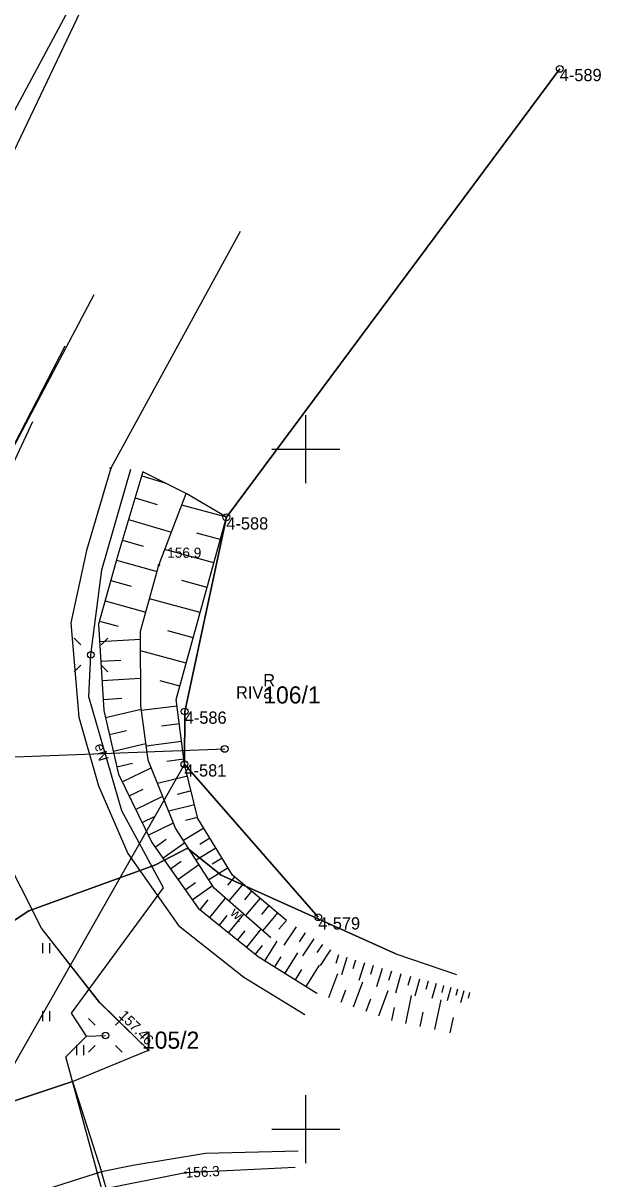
# Model space of a CAD drawing. Extents: x 5598798 to 5599616, y 5661498 to 5662453.
# Drawn here: x 5599229.2 to 5599271.7, y 5662046.3 to 5662131.3 of the extents above; entities that cross this region are included whole.
import ezdxf

# ---------------------------------------------------------------- set-up
doc = ezdxf.new("R2010")
doc.units = 0
for name, color, linetype in [('BUBZ_L_1', 7, 'Continuous'), ('Dzialki', 7, 'Continuous'), ('Kontury', 7, 'Continuous'), ('KTJZ_L_0', 7, 'Continuous'), ('KTKR_L_0', 7, 'Continuous'), ('Numery_dzialek', 7, 'Continuous'), ('Numery_konturow', 7, 'Continuous'), ('Numery_punktow', 7, 'Continuous'), ('Numery_uzytkow', 7, 'Continuous'), ('Podzial_sekcyjny_krzyze', 7, 'Continuous'), ('PTRW_E_T_0', 7, 'Continuous'), ('PTRW_L_1', 7, 'Continuous'), ('PTTU_L_2', 7, 'Continuous'), ('Punkty', 7, 'Continuous'), ('RTPW_T_0', 7, 'Continuous'), ('RTPW_T_1', 7, 'Continuous'), ('SUOE_L_1', 7, 'Continuous'), ('SUOW_L_0', 7, 'Continuous'), ('SUPE_E_T_3', 7, 'Continuous'), ('SUPE_L_3', 7, 'Continuous'), ('SUPT_L_0', 7, 'Continuous'), ('SUPW_L_0', 7, 'Continuous'), ('SUSM_T_0', 7, 'Continuous'), ('SUSM_T_3', 7, 'Continuous'), ('SUTE_T_0', 7, 'Continuous'), ('Uzytki', 7, 'Continuous')]:
    doc.layers.add(name, color=color, linetype=linetype)

# ---------------------------------------------------------------- blocks, each defined once
blk = doc.blocks.new('GRT')
blk.add_circle((0, 0), 0.25)
blk = doc.blocks.new('POINT_DISPLAY')
blk.add_line((0, 0), (0, 0))
blk = doc.blocks.new('2_PTTU04')
for p, q in [((-0.2625, -0.375), (-0.2625, 0.375)), ((0.2625, -0.375), (0.2625, 0.375))]:
    blk.add_line(p, q)
blk = doc.blocks.new('2_RTPW02')
blk.add_circle((0, 0), 0.045)
blk = doc.blocks.new('2_RTPW01')
blk.add_circle((0, 0), 0.045)
blk = doc.blocks.new('4_SUSM04_01')
blk.add_circle((0, 0), 0.25)
blk = doc.blocks.new('4_SUSM01')
for p, q in [((-0.74249, 0.74249), (-1.23746, 1.23746)), ((0.74249, 0.74249), (1.23746, 1.23746)), ((-0.74249, -0.74249), (-1.23746, -1.23746)), ((0.74249, -0.74249), (1.23746, -1.23746))]:
    blk.add_line(p, q)
blk.add_circle((0, 0), 0.245)
blk = doc.blocks.new('4_SUPS01_03')
blk.add_circle((0, 0), 0.0625)

msp = doc.modelspace()

# ---------------------------------------------------------------- linework, layer by layer
at = {"layer": 'BUBZ_L_1'}
for p, q in [((5599238.041933, 5662098.343835), (5599236.200458, 5662092.209108)), ((5599241.209969, 5662096.735049), (5599238.041933, 5662098.343835)), ((5599237.95, 5662098.037567), (5599239.649783, 5662097.527339)), ((5599239.218497, 5662091.477328), (5599241.209969, 5662096.735049)), ((5599244.17, 5662094.99), (5599241.209969, 5662096.735049)), ((5599237.461427, 5662096.409927), (5599239.089068, 5662095.921354)), ((5599244.17, 5662094.99), (5599240.890082, 5662095.890509)), ((5599236.989507, 5662094.837764), (5599240.133834, 5662093.893924)), ((5599240.493059, 5662081.597496), (5599244.17, 5662094.99)), ((5599236.533673, 5662093.319187), (5599238.05225, 5662092.863352)), ((5599243.719746, 5662093.350041), (5599242.002379, 5662093.821548)), ((5599243.248239, 5662091.632674), (5599239.651384, 5662092.620199)), ((5599236.200458, 5662092.209108), (5599234.785322, 5662087.124562)), ((5599236.095205, 5662091.830937), (5599239.084691, 5662090.9989)), ((5599237.858358, 5662086.614136), (5599239.218497, 5662091.477328)), ((5599235.679449, 5662090.337136), (5599237.173249, 5662089.92138)), ((5599242.754477, 5662089.834247), (5599240.899181, 5662090.343622)), ((5599242.245101, 5662087.97895), (5599238.525673, 5662089.000127)), ((5599235.263954, 5662088.844277), (5599238.249673, 5662088.013288)), ((5599234.848675, 5662087.352188), (5599236.213827, 5662086.972237)), ((5599234.785322, 5662087.124562), (5599235.159423, 5662080.790076)), ((5599237.872927, 5662081.131883), (5599237.858358, 5662086.614136)), ((5599241.734513, 5662086.119236), (5599239.87037, 5662086.631041)), ((5599234.859976, 5662085.860472), (5599237.85989, 5662086.03764)), ((5599241.222708, 5662084.255093), (5599237.862175, 5662085.177735)), ((5599234.946131, 5662084.401648), (5599236.404955, 5662084.487803)), ((5599235.029924, 5662082.982829), (5599237.867562, 5662083.150413)), ((5599240.761387, 5662082.574827), (5599239.314184, 5662082.97216)), ((5599235.111418, 5662081.602917), (5599236.49133, 5662081.684411)), ((5599241.09, 5662076.83), (5599240.493059, 5662081.597496)), ((5599235.159423, 5662080.790076), (5599236.246664, 5662076.092562)), ((5599235.280013, 5662080.269056), (5599237.908627, 5662080.877449)), ((5599238.434054, 5662077.132746), (5599237.872927, 5662081.131883)), ((5599240.553597, 5662081.114011), (5599237.921673, 5662080.784466)), ((5599240.718369, 5662079.798049), (5599239.412172, 5662079.634499)), ((5599235.571351, 5662079.010305), (5599236.830102, 5662079.301643)), ((5599235.850375, 5662077.804761), (5599238.261461, 5662078.362808)), ((5599240.881919, 5662078.491852), (5599238.28891, 5662078.16718)), ((5599240.438524, 5662072.135928), (5599238.434054, 5662077.132746)), ((5599241.044255, 5662077.195348), (5599239.789616, 5662077.038254)), ((5599236.117604, 5662076.650177), (5599237.272188, 5662076.917406)), ((5599236.516739, 5662075.53738), (5599238.656476, 5662076.578283)), ((5599242.073443, 5662072.833399), (5599241.09, 5662076.83)), ((5599236.246664, 5662076.092562), (5599238.692023, 5662071.065747)), ((5599241.304148, 5662075.959726), (5599239.12019, 5662075.42232)), ((5599237.019255, 5662074.504381), (5599238.052254, 5662075.006897)), ((5599237.504453, 5662073.506981), (5599239.499253, 5662074.477377)), ((5599241.572851, 5662074.867747), (5599240.557937, 5662074.618007)), ((5599241.822591, 5662073.852833), (5599239.936015, 5662073.388603)), ((5599237.97293, 5662072.543953), (5599238.935958, 5662073.01243)), ((5599242.054706, 5662072.909544), (5599241.177989, 5662072.693811)), ((5599244.61902, 5662068.679272), (5599242.073443, 5662072.833399)), ((5599238.425263, 5662071.614112), (5599240.284945, 5662072.518778)), ((5599243.270225, 5662067.718177), (5599240.438524, 5662072.135928)), ((5599242.504209, 5662072.130432), (5599241.023604, 5662071.223143)), ((5599238.692023, 5662071.065747), (5599242.092789, 5662066.260741)), ((5599238.926508, 5662070.734438), (5599239.75557, 5662071.321211)), ((5599239.500107, 5662069.923989), (5599241.121005, 5662071.071187)), ((5599242.957853, 5662071.390129), (5599242.225045, 5662070.941077)), ((5599243.406906, 5662070.657321), (5599241.956127, 5662069.768309)), ((5599240.060828, 5662069.131736), (5599240.853081, 5662069.692457)), ((5599240.60896, 5662068.35727), (5599242.157892, 5662069.453534)), ((5599243.851412, 5662069.931932), (5599243.133366, 5662069.491926)), ((5599244.291418, 5662069.213886), (5599242.869864, 5662068.342783)), ((5599244.777246, 5662068.546415), (5599244.257822, 5662067.927811)), ((5599248.58657, 5662065.347838), (5599244.61902, 5662068.679272)), ((5599241.144786, 5662067.600192), (5599241.901864, 5662068.136017)), ((5599241.668582, 5662066.860111), (5599243.148743, 5662067.907702)), ((5599247.44504, 5662064.071302), (5599243.270225, 5662067.718177)), ((5599245.395849, 5662068.026992), (5599244.346854, 5662066.777698)), ((5599242.246514, 5662066.136968), (5599242.830797, 5662066.862643)), ((5599242.958865, 5662065.563413), (5599244.105974, 5662066.988116)), ((5599246.020496, 5662067.502494), (5599245.490874, 5662066.871744)), ((5599246.651246, 5662066.972872), (5599245.581654, 5662065.699048)), ((5599242.092789, 5662066.260741), (5599246.515773, 5662062.699545)), ((5599247.288158, 5662066.438076), (5599246.748137, 5662065.794942)), ((5599243.657198, 5662065.001146), (5599244.219466, 5662065.699479)), ((5599244.341789, 5662064.449943), (5599245.444195, 5662065.819124)), ((5599247.931292, 5662065.898055), (5599246.840699, 5662064.59922)), ((5599248.58071, 5662065.352758), (5599248.033101, 5662064.700587)), ((5599245.012908, 5662063.909587), (5599245.553264, 5662064.580706)), ((5599245.67082, 5662063.379864), (5599246.730265, 5662064.695688)), ((5599249.287919, 5662064.878435), (5599248.38993, 5662063.536722)), ((5599249.958776, 5662064.429441), (5599249.526639, 5662063.783772)), ((5599246.315785, 5662062.860566), (5599246.835083, 5662063.505531)), ((5599247.009708, 5662062.389245), (5599247.903473, 5662063.811939)), ((5599250.604445, 5662063.997304), (5599249.772621, 5662062.75445)), ((5599251.225872, 5662063.581392), (5599250.825575, 5662062.983297)), ((5599246.515773, 5662062.699545), (5599250.819213, 5662059.996037)), ((5599247.737832, 5662061.931823), (5599248.195254, 5662062.659947)), ((5599248.483128, 5662061.463613), (5599249.419548, 5662062.954205)), ((5599251.823967, 5662063.181096), (5599251.053433, 5662062.029818)), ((5599252.407718, 5662062.812865), (5599252.215012, 5662062.187745)), ((5599253.032838, 5662062.620159), (5599252.641622, 5662061.351091)), ((5599249.246001, 5662060.98436), (5599249.725254, 5662061.747234)), ((5599250.026866, 5662060.493805), (5599251.007977, 5662062.055535)), ((5599253.667372, 5662062.424552), (5599253.468818, 5662061.780461)), ((5599254.311462, 5662062.225998), (5599253.908375, 5662060.918417)), ((5599254.965253, 5662062.024454), (5599254.760674, 5662061.360817)), ((5599255.62889, 5662061.819875), (5599255.21357, 5662060.472612)), ((5599251.711207, 5662059.668399), (5599252.364094, 5662061.445884)), ((5599253.519662, 5662059.004137), (5599254.187745, 5662060.822994)), ((5599256.302522, 5662061.612215), (5599256.091734, 5662060.928438)), ((5599256.98836, 5662061.408569), (5599256.608019, 5662059.996322)), ((5599257.694484, 5662061.218399), (5599257.514954, 5662060.551784)), ((5599258.361099, 5662061.038868), (5599258.023279, 5662059.784508)), ((5599258.988279, 5662060.869958), (5599258.829361, 5662060.27988)), ((5599250.822465, 5662059.994842), (5599250.833856, 5662060.025856)), ((5599252.610233, 5662059.338178), (5599252.940454, 5662060.237205)), ((5599255.370211, 5662058.324413), (5599256.053844, 5662060.185606)), ((5599259.578357, 5662060.711041), (5599259.279324, 5662059.600699)), ((5599260.133528, 5662060.561524), (5599259.992856, 5662060.039195)), ((5599260.655857, 5662060.420852), (5599260.391156, 5662059.437993)), ((5599261.147286, 5662060.288502), (5599261.022765, 5662059.826144)), ((5599261.609644, 5662060.163981), (5599261.375335, 5662059.293968)), ((5599262.044651, 5662060.046827), (5599261.934427, 5662059.637554)), ((5599254.439614, 5662058.66623), (5599254.777521, 5662059.586182)), ((5599257.353058, 5662057.770992), (5599257.778737, 5662059.820295)), ((5599259.497692, 5662057.32551), (5599259.949908, 5662059.502565)), ((5599256.328406, 5662057.983832), (5599256.529166, 5662058.950327)), ((5599258.409164, 5662057.551618), (5599258.628538, 5662058.607725)), ((5599260.619636, 5662057.092461), (5599260.852685, 5662058.214405))]:
    msp.add_line(p, q, dxfattribs=at)
at = {"layer": 'Dzialki'}
for p, q in [((5599217.72, 5662099.21), (5599239.49, 5662144.83)), ((5599268.67, 5662127.96), (5599244.17, 5662094.99)), ((5599244.17, 5662094.99), (5599241.11, 5662080.71)), ((5599241.11, 5662080.71), (5599241.09, 5662076.83)), ((5599241.09, 5662076.83), (5599221.18, 5662041.76)), ((5599250.92, 5662065.58), (5599241.09, 5662076.83))]:
    msp.add_line(p, q, dxfattribs=at)
at = {"layer": 'Kontury'}
for p, q in [((5599244.17, 5662094.99), (5599268.67, 5662127.96)), ((5599241.11, 5662080.71), (5599244.17, 5662094.99)), ((5599241.09, 5662076.83), (5599241.11, 5662080.71)), ((5599250.92, 5662065.58), (5599241.09, 5662076.83))]:
    msp.add_line(p, q, dxfattribs=at)
at = {"layer": 'KTJZ_L_0'}
for p, q in [((5599245.194235, 5662115.994643), (5599235.675, 5662098.600183)), ((5599222.646593, 5662086.37844), (5599229.944352, 5662102.03161)), ((5599235.675, 5662098.600183), (5599233.881705, 5662092.546589)), ((5599233.881705, 5662092.546589), (5599232.742238, 5662087.218191)), ((5599232.742238, 5662087.218191), (5599233.339967, 5662080.288504)), ((5599233.339967, 5662080.288504), (5599234.785147, 5662075.248961)), ((5599234.785147, 5662075.248961), (5599236.929384, 5662070.265325)), ((5599230.59085, 5662064.788744), (5599227.58506, 5662070.703245)), ((5599236.929384, 5662070.265325), (5599240.661273, 5662064.977615)), ((5599234.857032, 5662059.323088), (5599230.59085, 5662064.788744)), ((5599240.661273, 5662064.977615), (5599245.449694, 5662061.184611)), ((5599245.449694, 5662061.184611), (5599249.944262, 5662058.435424)), ((5599238.438465, 5662055.812797), (5599234.857032, 5662059.323088)), ((5599232.86, 5662053.51), (5599238.438465, 5662055.812797)), ((5599232.86, 5662053.51), (5599224.74, 5662050.8)), ((5599232.86, 5662053.51), (5599235, 5662046.87)), ((5599242.643296, 5662048.204737), (5599237.300603, 5662047.33295)), ((5599249.452284, 5662048.389512), (5599242.643296, 5662048.204737)), ((5599237.300603, 5662047.33295), (5599235, 5662046.87)), ((5599235, 5662046.87), (5599231.08, 5662045.62)), ((5599235.55, 5662044.89), (5599235, 5662046.87))]:
    msp.add_line(p, q, dxfattribs=at)
at = {"layer": 'KTKR_L_0'}
for p, q in [((5599230.59, 5662064.79), (5599227.59, 5662070.7)), ((5599234.86, 5662059.32), (5599230.59, 5662064.79)), ((5599238.44, 5662055.81), (5599234.86, 5662059.32)), ((5599232.86, 5662053.51), (5599238.44, 5662055.81)), ((5599224.74, 5662050.8), (5599232.86, 5662053.51))]:
    msp.add_line(p, q, dxfattribs=at)
at = {"layer": 'Podzial_sekcyjny_krzyze'}
for p, q in [((5599250, 5662097.5), (5599250, 5662102.5)), ((5599247.5, 5662100), (5599252.5, 5662100)), ((5599250, 5662047.5), (5599250, 5662052.5)), ((5599247.5, 5662050), (5599252.5, 5662050))]:
    msp.add_line(p, q, dxfattribs=at)
at = {"layer": 'PTRW_L_1'}
for p, q in [((5599239.218497, 5662091.477328), (5599241.209969, 5662096.735049)), ((5599237.858358, 5662086.614136), (5599239.218497, 5662091.477328)), ((5599237.872927, 5662081.131883), (5599237.858358, 5662086.614136)), ((5599238.434054, 5662077.132746), (5599237.872927, 5662081.131883)), ((5599240.438524, 5662072.135928), (5599238.434054, 5662077.132746)), ((5599243.270225, 5662067.718177), (5599240.438524, 5662072.135928)), ((5599247.44504, 5662064.071302), (5599243.270225, 5662067.718177))]:
    msp.add_line(p, q, dxfattribs=at)
at = {"layer": 'PTTU_L_2'}
for p, q in [((5599230.59, 5662064.79), (5599227.59, 5662070.7)), ((5599234.86, 5662059.32), (5599230.59, 5662064.79)), ((5599238.44, 5662055.81), (5599234.86, 5662059.32)), ((5599232.86, 5662053.51), (5599238.44, 5662055.81)), ((5599224.74, 5662050.8), (5599232.86, 5662053.51))]:
    msp.add_line(p, q, dxfattribs=at)
at = {"layer": 'SUOE_L_1'}
for p, q in [((5599232.794181, 5662058.525848), (5599239.547678, 5662067.753624)), ((5599232.794181, 5662058.525848), (5599239.547678, 5662067.753624)), ((5599235.009357, 5662045.580071), (5599232.376942, 5662055.314856)), ((5599235.009357, 5662045.580071), (5599232.376942, 5662055.314856))]:
    msp.add_line(p, q, dxfattribs=at)
at = {"layer": 'SUOW_L_0'}
msp.add_line((5599229.661799, 5662066.048231), (5599238.919973, 5662069.40014), dxfattribs=at)
msp.add_line((5599229.661799, 5662066.048231), (5599238.919973, 5662069.40014), dxfattribs=at)
at = {"layer": 'SUPE_L_3'}
for p, q in [((5599235.014611, 5662091.121655), (5599237.157429, 5662098.523825)), ((5599234.216268, 5662084.870572), (5599235.014611, 5662091.121655)), ((5599234.076062, 5662081.795938), (5599234.216268, 5662084.870572)), ((5599236.498027, 5662073.397002), (5599234.076062, 5662081.795938)), ((5599207.821671, 5662076.607039), (5599244.04787, 5662077.960672)), ((5599239.547678, 5662067.753624), (5599236.498027, 5662073.397002)), ((5599232.794181, 5662058.525848), (5599239.547678, 5662067.753624)), ((5599233.903225, 5662056.830244), (5599232.794181, 5662058.525848)), ((5599232.376942, 5662055.314856), (5599233.903225, 5662056.830244)), ((5599233.903225, 5662056.830244), (5599235.282477, 5662056.891607)), ((5599235.009357, 5662045.580071), (5599232.376942, 5662055.314856)), ((5599235.009357, 5662045.580071), (5599241.174509, 5662046.800708)), ((5599241.174509, 5662046.800708), (5599249.218892, 5662047.213655))]:
    msp.add_line(p, q, dxfattribs=at)
at = {"layer": 'SUPT_L_0'}
for p, q in [((5599224.612833, 5662092.746111), (5599234.454092, 5662111.378469)), ((5599227.058149, 5662097.403859), (5599232.318985, 5662107.598181))]:
    msp.add_line(p, q, dxfattribs=at)
at = {"layer": 'SUPW_L_0'}
for p, q in [((5599246.158544, 5662157.63618), (5599220.8293, 5662110.428489)), ((5599241.322352, 5662070.665314), (5599238.919973, 5662069.40014)), ((5599238.919973, 5662069.40014), (5599241.322352, 5662070.665314)), ((5599243.778833, 5662068.670181), (5599241.322352, 5662070.665314)), ((5599241.322352, 5662070.665314), (5599243.778833, 5662068.670181)), ((5599238.919973, 5662069.40014), (5599229.661799, 5662066.048231)), ((5599229.661799, 5662066.048231), (5599238.919973, 5662069.40014)), ((5599256.625966, 5662062.899324), (5599243.778833, 5662068.670181)), ((5599243.778833, 5662068.670181), (5599256.625966, 5662062.899324)), ((5599229.661799, 5662066.048231), (5599224.505699, 5662062.689511)), ((5599224.505699, 5662062.689511), (5599229.661799, 5662066.048231)), ((5599256.625966, 5662062.899324), (5599261.072576, 5662061.379626))]:
    msp.add_line(p, q, dxfattribs=at)
at = {"layer": 'Uzytki'}
for p, q in [((5599268.67, 5662127.96), (5599244.17, 5662094.99)), ((5599244.17, 5662094.99), (5599241.11, 5662080.71)), ((5599241.11, 5662080.71), (5599241.09, 5662076.83)), ((5599241.09, 5662076.83), (5599250.92, 5662065.58))]:
    msp.add_line(p, q, dxfattribs=at)

# ---------------------------------------------------------------- block references
at = {"layer": 'BUBZ_L_1'}
msp.add_blockref('POINT_DISPLAY', (5599261.770744, 5662056.853354), dxfattribs=at)
at = {"layer": 'PTTU_L_2'}
for p in [(5599230.94, 5662063.31), (5599230.94, 5662058.31), (5599233.44, 5662055.81)]:
    msp.add_blockref('2_PTTU04', p, dxfattribs=at)
at = {"layer": 'Punkty'}
for p in [(5599268.67, 5662127.96), (5599244.17, 5662094.99), (5599241.11, 5662080.71), (5599241.09, 5662076.83), (5599250.92, 5662065.58)]:
    msp.add_blockref('GRT', p, dxfattribs=at)
at = {"layer": 'RTPW_T_0'}
msp.add_blockref('2_RTPW01', (5599239.218497, 5662091.477328), dxfattribs=at)
at = {"layer": 'RTPW_T_1'}
for p in [(5599235.675, 5662098.600183), (5599238.438465, 5662055.812797)]:
    msp.add_blockref('2_RTPW02', p, dxfattribs=at)
at = {"layer": 'SUSM_T_0'}
for p in [(5599234.216268, 5662084.870572), (5599235.282477, 5662056.891607)]:
    msp.add_blockref('4_SUSM01', p, dxfattribs=at)
at = {"layer": 'SUSM_T_3'}
msp.add_blockref('4_SUSM04_01', (5599244.04787, 5662077.960672), dxfattribs=at)
at = {"layer": 'SUTE_T_0'}
msp.add_blockref('4_SUPS01_03', (5599241.174509, 5662046.800708), dxfattribs=at)

# ---------------------------------------------------------------- texts
at = {"layer": 'Numery_dzialek'}
for s, p in [('106/1', (5599246.881715, 5662081.299888)), ('105/2', (5599237.965698, 5662055.913919))]:
    msp.add_text(s, height=1.26, dxfattribs=at).set_placement(p)
at = {"layer": 'Numery_konturow'}
msp.add_text('RIVa', height=0.9, dxfattribs=at).set_placement((5599244.877955, 5662081.659888))
at = {"layer": 'Numery_punktow'}
for s, p in [('4-589', (5599268.67, 5662127.06)), ('4-588', (5599244.17, 5662094.09)), ('4-586', (5599241.11, 5662079.81)), ('4-581', (5599241.09, 5662075.93)), ('4-579', (5599250.92, 5662064.68))]:
    msp.add_text(s, height=0.9, dxfattribs=at).set_placement(p)
at = {"layer": 'Numery_uzytkow'}
msp.add_text('R', height=0.9, dxfattribs=at).set_placement((5599246.881715, 5662082.559888))
at = {"layer": 'PTRW_E_T_0'}
msp.add_text('w.', height=0.75, rotation=317.779165, dxfattribs=at).set_placement((5599244.40449, 5662065.818501))
at = {"layer": 'RTPW_T_0'}
msp.add_text('156.9', height=0.75, rotation=359.648497, dxfattribs=at).set_placement((5599239.817906, 5662092.019896))
at = {"layer": 'RTPW_T_1'}
msp.add_text('157.46', height=0.75, rotation=314.440125, dxfattribs=at).set_placement((5599236.216211, 5662058.303927))
at = {"layer": 'SUPE_E_T_3'}
msp.add_text('eN', height=0.75, rotation=286.085749, dxfattribs=at).set_placement((5599234.471951, 5662078.232555))
at = {"layer": 'SUTE_T_0'}
msp.add_text('156.3', height=0.75, rotation=2.938638, dxfattribs=at).set_placement((5599241.193734, 5662046.426201))

doc.saveas('drawing.dxf')
